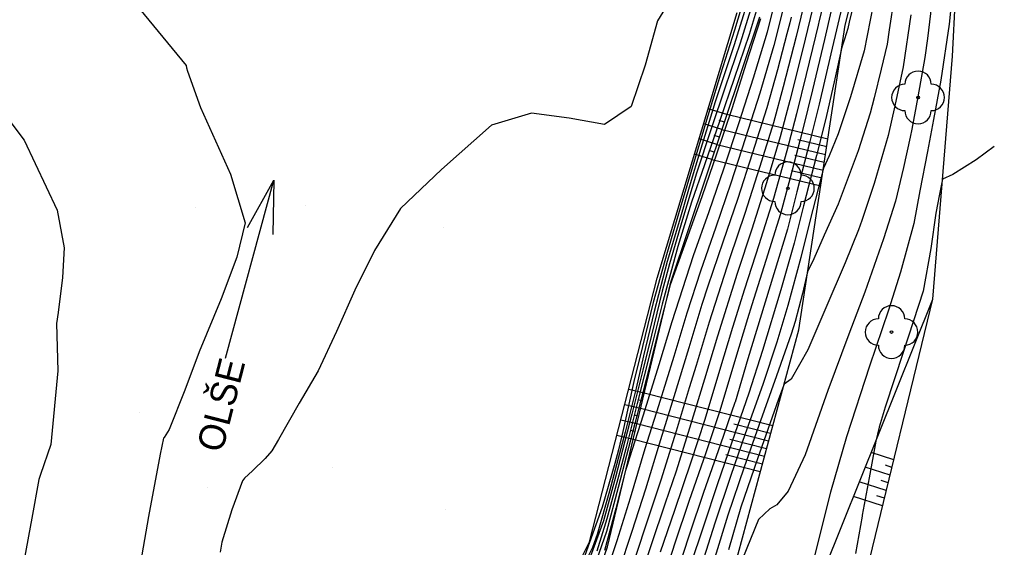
# Model space of a CAD drawing. Extents: x -448957 to -448612, y -1107690 to -1107245.
# Drawn here: x -448689.52 to -448652.59, y -1107456.66 to -1107436.62 of the extents above; entities that cross this region are included whole.
import ezdxf

# ---------------------------------------------------------------- set-up
doc = ezdxf.new("R2010")
doc.units = 0
for name, color, linetype in [('22', 7, 'Continuous'), ('Default', 7, 'Continuous'), ('Vrstva 1', 7, 'Continuous'), ('Vrstva 14', 7, 'Continuous'), ('Vrstva 15', 7, 'Continuous'), ('Vrstva 16', 7, 'Continuous'), ('Vrstva 17', 7, 'Continuous'), ('Vrstva 22', 7, 'Continuous'), ('Vrstva 45', 7, 'Continuous')]:
    doc.layers.add(name, color=color, linetype=linetype)

# ---------------------------------------------------------------- blocks, each defined once
blk = doc.blocks.new('STROM$5')
at = {"layer": '22'}
blk.add_circle((0, 0), 0.5, dxfattribs=at)
for centre, start, end in [((0, 5), 0, 180), ((-5, 0), 90, 270), ((5, 0), 270, 90), ((0, -5), 180, 0)]:
    blk.add_arc(centre, 5, start, end, dxfattribs=at)
blk = doc.blocks.new('POINT_DISPLAY')
at = {"layer": 'Default'}
blk.add_line((0, 0), (0, 0), dxfattribs=at)
blk = doc.blocks.new('TOK')
at = {"layer": 'Default'}
for p, q in [((-5, 50), (0, 70)), ((0, 0), (0, 70)), ((0, 70), (5, 50))]:
    blk.add_line(p, q, dxfattribs=at)

msp = doc.modelspace()

# ---------------------------------------------------------------- linework, layer by layer
at = {"layer": 'Vrstva 14'}
for p, q in [((-448658.208, -1107436.835), (-448656.283, -1107429.269)), ((-448654.143, -1107438.013), (-448653.744, -1107430.309)), ((-448665.335, -1107446.444), (-448662.303, -1107436.351)), ((-448664.827, -1107446.588), (-448661.451, -1107436.528)), ((-448659.968, -1107448.397), (-448658.208, -1107436.835)), ((-448654.891, -1107447.236), (-448654.143, -1107438.013)), ((-448667.905, -1107456.447), (-448665.335, -1107446.444)), ((-448667.226, -1107456.63), (-448664.827, -1107446.588)), ((-448660.072, -1107460.14), (-448654.891, -1107447.236)), ((-448657.767, -1107459.1), (-448654.891, -1107447.236)), ((-448662.598, -1107458.098), (-448659.968, -1107448.397)), ((-448671.17, -1107462.969), (-448667.905, -1107456.447)), ((-448669.745, -1107463.846), (-448667.226, -1107456.63))]:
    msp.add_line(p, q, dxfattribs=at)
at = {"layer": 'Vrstva 15'}
for p, q in [((-448662.694, -1107440.233), (-448663.402, -1107440.008)), ((-448662.885, -1107440.802), (-448663.574, -1107440.583)), ((-448662.79, -1107440.518), (-448662.992, -1107440.453)), ((-448658.866, -1107441.16), (-448662.694, -1107440.233)), ((-448658.957, -1107441.755), (-448662.886, -1107440.804)), ((-448663.076, -1107441.371), (-448663.747, -1107441.158)), ((-448662.981, -1107441.087), (-448663.178, -1107441.024)), ((-448658.912, -1107441.457), (-448660.005, -1107441.193)), ((-448663.172, -1107441.655), (-448663.363, -1107441.595)), ((-448659.048, -1107442.35), (-448663.078, -1107441.375)), ((-448663.267, -1107441.94), (-448663.92, -1107441.732)), ((-448659.138, -1107442.946), (-448663.269, -1107441.946)), ((-448659.002, -1107442.053), (-448660.125, -1107441.781)), ((-448659.093, -1107442.648), (-448660.244, -1107442.369)), ((-448665.835, -1107450.806), (-448666.419, -1107450.662)), ((-448660.958, -1107452.05), (-448665.835, -1107450.806)), ((-448665.974, -1107451.39), (-448666.568, -1107451.243)), ((-448665.904, -1107451.098), (-448666.071, -1107451.057)), ((-448666.044, -1107451.682), (-448666.214, -1107451.64)), ((-448661.115, -1107452.629), (-448665.974, -1107451.39)), ((-448666.114, -1107451.974), (-448666.717, -1107451.824)), ((-448661.272, -1107453.208), (-448666.114, -1107451.974)), ((-448661.037, -1107452.339), (-448662.43, -1107451.984)), ((-448666.253, -1107452.557), (-448666.867, -1107452.405)), ((-448666.183, -1107452.265), (-448666.356, -1107452.223)), ((-448661.429, -1107453.787), (-448666.253, -1107452.557)), ((-448661.194, -1107452.918), (-448662.582, -1107452.564)), ((-448656.368, -1107453.328), (-448657.226, -1107453.053)), ((-448661.351, -1107453.498), (-448662.734, -1107453.145)), ((-448656.509, -1107453.912), (-448657.451, -1107453.611)), ((-448656.439, -1107453.62), (-448656.684, -1107453.541)), ((-448656.651, -1107454.497), (-448657.675, -1107454.169)), ((-448656.58, -1107454.205), (-448656.849, -1107454.119)), ((-448656.793, -1107455.082), (-448657.899, -1107454.728)), ((-448656.722, -1107454.789), (-448657.014, -1107454.696))]:
    msp.add_line(p, q, dxfattribs=at)
at = {"layer": 'Vrstva 16'}
for points in [[(-448658.884, -1107435.394), (-448659.196, -1107436.656), (-448659.24, -1107436.841), (-448659.339, -1107437.253), (-448659.691, -1107438.711), (-448660.061, -1107440.209), (-448660.421, -1107441.602), (-448660.929, -1107443.41), (-448661.481, -1107445.174), (-448662.024, -1107446.858), (-448662.485, -1107448.308), (-448662.975, -1107449.948), (-448663.537, -1107451.805), (-448664.059, -1107453.419), (-448664.687, -1107455.252), (-448665.224, -1107456.837)], [(-448656.353, -1107435.763), (-448656.541, -1107437.012), (-448656.624, -1107437.555), (-448656.842, -1107438.504), (-448657.107, -1107439.601), (-448657.26, -1107440.174), (-448657.713, -1107441.601), (-448658.476, -1107443.635), (-448659.008, -1107444.814), (-448659.401, -1107445.705), (-448659.634, -1107446.201), (-448659.835, -1107447.024), (-448660.11, -1107448.082), (-448660.255, -1107448.561), (-448660.815, -1107450.145), (-448661.489, -1107452.03), (-448662.038, -1107453.611), (-448662.661, -1107455.437), (-448663.147, -1107457.038)], [(-448662.06, -1107435.897), (-448662.413, -1107437.023), (-448662.941, -1107438.703), (-448663.42, -1107440.28), (-448663.926, -1107441.962), (-448664.465, -1107443.78), (-448664.963, -1107445.464), (-448665.489, -1107447.36), (-448665.899, -1107449.033), (-448666.221, -1107450.357), (-448666.44, -1107451.337), (-448666.635, -1107452.256), (-448666.802, -1107452.954), (-448666.942, -1107453.479), (-448667.421, -1107455.131), (-448668.15, -1107457.14)], [(-448660.911, -1107436.085), (-448661.171, -1107437.102), (-448661.702, -1107438.849), (-448662.257, -1107440.587), (-448662.815, -1107442.266), (-448663.38, -1107443.926), (-448663.971, -1107445.592), (-448664.789, -1107448.094), (-448665.276, -1107449.735), (-448665.874, -1107451.633), (-448666.391, -1107453.262), (-448666.468, -1107453.515), (-448666.535, -1107453.737), (-448666.904, -1107455.177), (-448667.34, -1107456.769)]]:
    msp.add_lwpolyline(points, dxfattribs=at)
at = {"layer": 'Vrstva 17'}
for points in [[(-448664.492, -1107435.301), (-448665.325, -1107436.669), (-448665.795, -1107438.36), (-448666.329, -1107439.921), (-448667.338, -1107440.602), (-448668.671, -1107440.37), (-448670.099, -1107440.182), (-448671.616, -1107440.636), (-448673.522, -1107442.311), (-448675.075, -1107443.801), (-448676.056, -1107445.395), (-448676.801, -1107446.901), (-448677.496, -1107448.467), (-448678.196, -1107449.958), (-448678.916, -1107451.183), (-448679.702, -1107452.565), (-448679.956, -1107452.996), (-448680.202, -1107453.281), (-448680.679, -1107453.756), (-448680.988, -1107454.024), (-448681.066, -1107454.13), (-448681.466, -1107455.235), (-448681.848, -1107456.464), (-448681.912, -1107456.843)], [(-448661.668, -1107435.165), (-448662.416, -1107437.581), (-448662.973, -1107439.259), (-448663.147, -1107439.783), (-448663.214, -1107439.997), (-448663.68, -1107441.522), (-448664.128, -1107442.988), (-448664.46, -1107444.119), (-448664.954, -1107445.804), (-448665.448, -1107447.709), (-448665.852, -1107449.383), (-448666.142, -1107450.608), (-448666.549, -1107452.28), (-448667.149, -1107454.519), (-448667.616, -1107456.174), (-448667.793, -1107456.661), (-448668.329, -1107457.75)], [(-448685.317, -1107435.775), (-448683.196, -1107438.369), (-448683.182, -1107438.46), (-448683.154, -1107438.582), (-448682.654, -1107439.965), (-448681.52, -1107442.492), (-448680.967, -1107444.34), (-448681.277, -1107445.637), (-448681.866, -1107447.227), (-448682.428, -1107448.568), (-448682.706, -1107449.239), (-448683.243, -1107450.692), (-448683.842, -1107452.18), (-448684.027, -1107452.482), (-448684.057, -1107452.514), (-448684.18, -1107453.125), (-448684.63, -1107455.487), (-448684.873, -1107456.934)], [(-448661.63, -1107435.712), (-448662.192, -1107437.521), (-448662.758, -1107439.197), (-448663.296, -1107440.776), (-448663.849, -1107442.452), (-448664.374, -1107444.213), (-448664.867, -1107445.899), (-448665.149, -1107446.935), (-448665.555, -1107448.609), (-448665.878, -1107449.937), (-448666.297, -1107451.606), (-448666.919, -1107453.993), (-448667.374, -1107455.652), (-448667.955, -1107457.229)], [(-448660.43, -1107435.692), (-448660.922, -1107437.611), (-448661.444, -1107439.414), (-448661.999, -1107441.157), (-448662.548, -1107442.839), (-448663.112, -1107444.5), (-448663.695, -1107446.169), (-448664.218, -1107447.768), (-448664.707, -1107449.409), (-448665.289, -1107451.29), (-448665.802, -1107452.922), (-448666.368, -1107454.783), (-448666.872, -1107456.411), (-448667.061, -1107456.982)], [(-448657.754, -1107435.469), (-448658.062, -1107436.728), (-448658.11, -1107436.97), (-448658.234, -1107437.369), (-448658.335, -1107437.668), (-448658.603, -1107438.875), (-448658.943, -1107440.375), (-448659.3, -1107441.786), (-448659.788, -1107443.695), (-448660.144, -1107445.117), (-448660.65, -1107446.88), (-448661.35, -1107449.186), (-448661.861, -1107450.808), (-448662.506, -1107452.659), (-448663.051, -1107454.242), (-448663.571, -1107455.808), (-448664.097, -1107457.397)], [(-448654.136, -1107435.532), (-448654.274, -1107436.795), (-448654.581, -1107438.931), (-448654.856, -1107440.424), (-448655.086, -1107441.632), (-448655.382, -1107443.12), (-448655.602, -1107444.36), (-448656.11, -1107446.218), (-448656.571, -1107447.657), (-448657.293, -1107449.776), (-448658.161, -1107452.467), (-448658.769, -1107454.559), (-448659.644, -1107458.039)], [(-448661.508, -1107436.057), (-448661.855, -1107437.188), (-448662.419, -1107438.865), (-448662.961, -1107440.461), (-448663.542, -1107442.134), (-448664.041, -1107443.552), (-448664.554, -1107445.235), (-448665.149, -1107447.424), (-448665.561, -1107449.095), (-448666.096, -1107451.2), (-448666.521, -1107452.867), (-448666.798, -1107453.914), (-448667.245, -1107455.575), (-448667.632, -1107456.805)], [(-448659.347, -1107435.791), (-448659.832, -1107437.784), (-448660.313, -1107439.693), (-448660.675, -1107441.071), (-448661.195, -1107442.822), (-448661.747, -1107444.582), (-448662.302, -1107446.261), (-448663.057, -1107448.635), (-448663.547, -1107450.275), (-448664.114, -1107452.138), (-448664.62, -1107453.769), (-448665.032, -1107454.98), (-448665.57, -1107456.565), (-448665.812, -1107457.283)], [(-448658.275, -1107435.895), (-448658.754, -1107437.921), (-448659.198, -1107439.834), (-448659.554, -1107441.258), (-448660.041, -1107443.166), (-448660.399, -1107444.575), (-448660.921, -1107446.28), (-448661.898, -1107449.498), (-448662.385, -1107451.14), (-448662.39, -1107451.156), (-448662.944, -1107452.736), (-448663.584, -1107454.572), (-448664.118, -1107456.158), (-448664.891, -1107458.545)], [(-448657.149, -1107436.06), (-448657.496, -1107437.812), (-448658.013, -1107439.561), (-448658.475, -1107440.959), (-448658.813, -1107441.799), (-448659.035, -1107442.27), (-448659.534, -1107444.224), (-448659.889, -1107445.659), (-448660.38, -1107447.481), (-448660.803, -1107448.874), (-448661.338, -1107450.477), (-448661.998, -1107452.345), (-448662.545, -1107453.927), (-448663.154, -1107455.737), (-448663.66, -1107457.333)], [(-448654.933, -1107436.081), (-448655.083, -1107437.34), (-448655.187, -1107438.065), (-448655.462, -1107439.559), (-448655.688, -1107440.779), (-448655.749, -1107441.084), (-448655.995, -1107442.242), (-448656.307, -1107443.512), (-448656.758, -1107444.945), (-448657.471, -1107446.968), (-448658.067, -1107448.561), (-448658.866, -1107450.697), (-448659.733, -1107453.145), (-448660.368, -1107454.527), (-448660.797, -1107455.048), (-448661.073, -1107455.188), (-448661.501, -1107455.603), (-448662.098, -1107457.091)], [(-448659.803, -1107436.165), (-448660.072, -1107437.27), (-448660.566, -1107439.178), (-448660.93, -1107440.54), (-448661.461, -1107442.234), (-448662.014, -1107443.989), (-448662.58, -1107445.665), (-448663.374, -1107448.11), (-448663.864, -1107449.75), (-448664.121, -1107450.605), (-448664.624, -1107452.24), (-448665.197, -1107454.11), (-448665.728, -1107455.705), (-448666.528, -1107458.116)], [(-448658.736, -1107436.276), (-448658.997, -1107437.381), (-448659.453, -1107439.293), (-448659.808, -1107440.729), (-448659.936, -1107441.231), (-448660.294, -1107442.634), (-448660.663, -1107443.998), (-448661.214, -1107445.766), (-448661.746, -1107447.454), (-448661.913, -1107447.98), (-448662.404, -1107449.62), (-448662.961, -1107451.472), (-448663.499, -1107453.07), (-448664.136, -1107454.912), (-448664.671, -1107456.498), (-448665.206, -1107458.153)], [(-448655.715, -1107436.441), (-448656.018, -1107438.421), (-448656.327, -1107439.905), (-448656.585, -1107441.024), (-448657.116, -1107442.841), (-448657.573, -1107444.254), (-448657.703, -1107444.609), (-448658.213, -1107445.858), (-448658.95, -1107447.561), (-448659.624, -1107449.155), (-448660.256, -1107450.269), (-448660.529, -1107450.466), (-448660.735, -1107451.033), (-448660.981, -1107451.715), (-448661.532, -1107453.296), (-448662.168, -1107455.136), (-448662.634, -1107456.744)], [(-448661.42, -1107436.592), (-448661.959, -1107438.284), (-448662.514, -1107440.018), (-448663.082, -1107441.693), (-448663.647, -1107443.353), (-448664.246, -1107445.016), (-448664.846, -1107446.692), (-448664.876, -1107446.792), (-448665.27, -1107448.359), (-448665.757, -1107450.287), (-448666.184, -1107451.953), (-448666.821, -1107454.387), (-448667.26, -1107456.05), (-448667.641, -1107457.136)], [(-448660.26, -1107436.54), (-448660.312, -1107436.755), (-448660.417, -1107437.161), (-448660.781, -1107438.527), (-448661.187, -1107439.978), (-448661.741, -1107441.726), (-448662.281, -1107443.411), (-448662.845, -1107445.074), (-448663.42, -1107446.746), (-448663.648, -1107447.443), (-448664.137, -1107449.083), (-448664.705, -1107450.948), (-448665.213, -1107452.581), (-448665.782, -1107454.447), (-448666.3, -1107456.058), (-448666.794, -1107457.549)], [(-448691.445, -1107438.436), (-448689.341, -1107441.199), (-448688.094, -1107443.86), (-448687.818, -1107445.288), (-448687.883, -1107446.408), (-448688.054, -1107447.743), (-448688.12, -1107448.155), (-448688.063, -1107449.96), (-448688.333, -1107452.747), (-448688.716, -1107453.89), (-448688.789, -1107454.084), (-448689.054, -1107455.542), (-448689.323, -1107457.059), (-448689.657, -1107458.521)], [(-448652.557, -1107441.445), (-448653.243, -1107441.947), (-448654.123, -1107442.499), (-448654.521, -1107442.677), (-448654.634, -1107443.256), (-448654.774, -1107443.975), (-448654.961, -1107445.318), (-448655.251, -1107446.935), (-448655.999, -1107449.217), (-448656.697, -1107451.33), (-448656.917, -1107452.098), (-448657.053, -1107452.621), (-448657.305, -1107454.014), (-448657.561, -1107455.436), (-448657.569, -1107455.478), (-448657.821, -1107456.89)]]:
    msp.add_lwpolyline(points, dxfattribs=at)

# ---------------------------------------------------------------- block references
at = {"layer": 'Vrstva 1', "xscale": 0.1, "yscale": 0.10000000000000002}
for p in [(-448658.208, -1107436.835), (-448654.143, -1107438.013), (-448665.335, -1107446.444), (-448664.827, -1107446.588), (-448654.891, -1107447.236), (-448659.968, -1107448.397), (-448667.905, -1107456.447), (-448667.226, -1107456.63)]:
    msp.add_blockref('POINT_DISPLAY', p, dxfattribs=at)
at = {"layer": 'Vrstva 14', "xscale": 0.1, "yscale": 0.10000000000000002}
for p in [(-448682.86, -1107443.741), (-448678.664, -1107443.686), (-448673.457, -1107444.534), (-448684.976, -1107451.523), (-448677.66, -1107453.61), (-448682.382, -1107454.398), (-448673.351, -1107455.214)]:
    msp.add_blockref('POINT_DISPLAY', p, dxfattribs=at)
at = {"layer": 'Vrstva 22', "xscale": 0.1, "yscale": 0.10000000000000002}
for p in [(-448655.448, -1107439.582), (-448660.381, -1107443.03), (-448656.453, -1107448.484)]:
    msp.add_blockref('STROM$5', p, dxfattribs=at)
at = {"layer": 'Vrstva 45', "xscale": 0.1, "yscale": 0.10000000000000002, "rotation": -15.24572582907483}
msp.add_blockref('TOK', (-448681.711, -1107449.472), dxfattribs=at)

# ---------------------------------------------------------------- texts
at = {"layer": 'Vrstva 45'}
msp.add_text('OLŠE', height=1, rotation=75.591, dxfattribs=at).set_placement((-448681.837, -1107453.1))

doc.saveas('drawing.dxf')
